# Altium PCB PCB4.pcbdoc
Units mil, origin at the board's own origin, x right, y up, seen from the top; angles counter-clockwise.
Board outline 2975.8 x 1882.95 mil, 2 copper layers (Top Layer, Bottom Layer); 34 components, 33 nets, 157 pads, 29 vias.
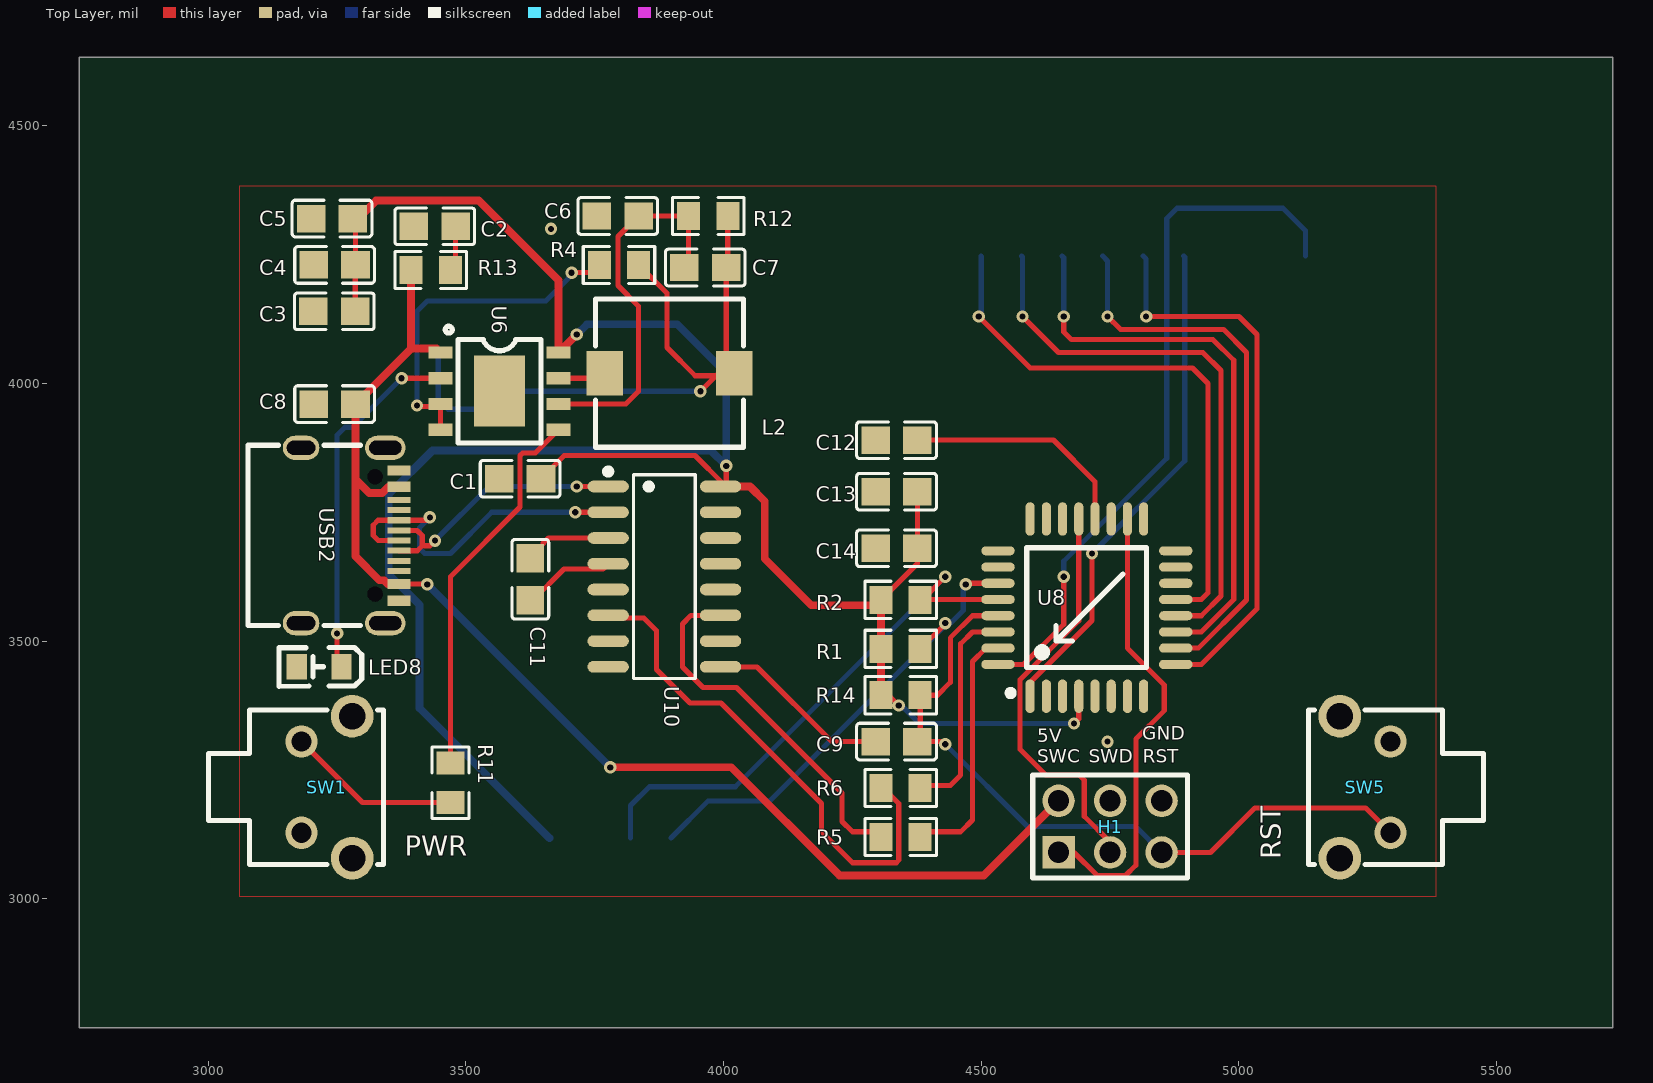
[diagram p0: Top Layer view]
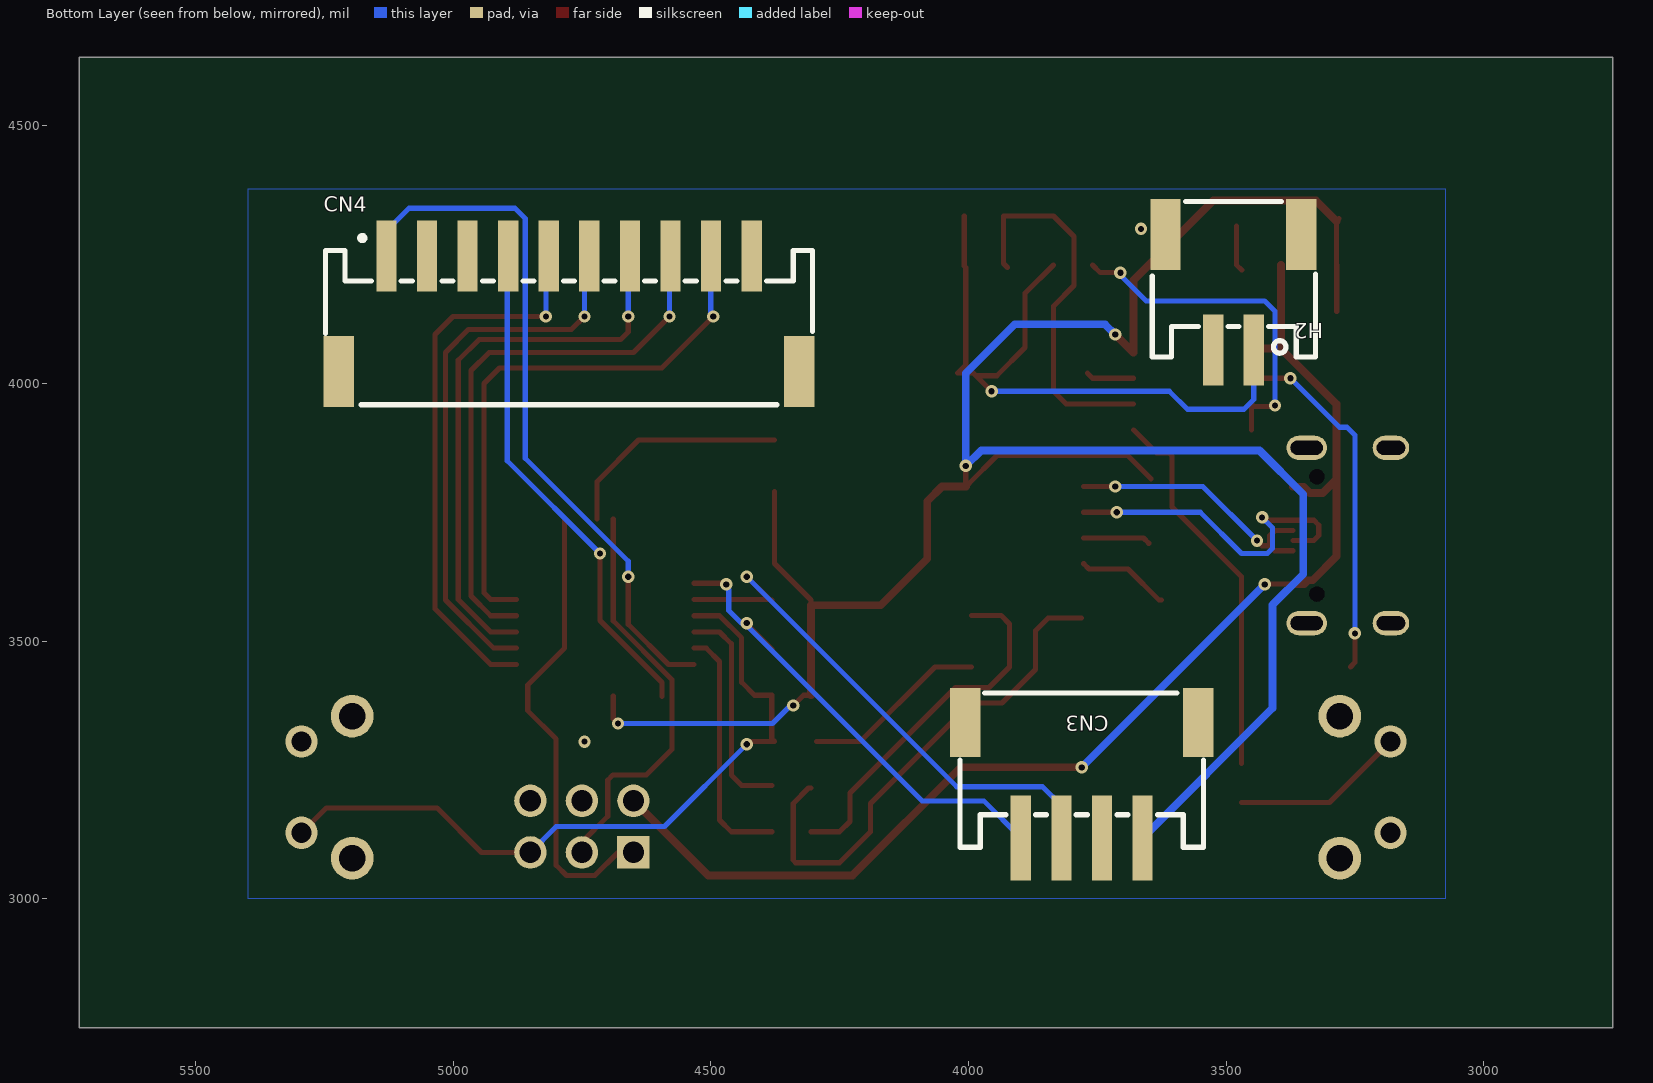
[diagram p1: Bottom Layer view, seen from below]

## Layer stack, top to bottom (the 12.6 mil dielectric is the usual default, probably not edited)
Top Solder: solder mask 0.4, Solder Resist, Dk 3.5
Top Layer: signal copper 1.4
Dielectric 1: dielectric 12.6, FR-4, Dk 4.8
Bottom Layer: signal copper 1.4
Bottom Solder: solder mask 0.4, Solder Resist, Dk 3.5

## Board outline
5725.8,2750 2750,2750 2750,4632.95 5725.8,4632.95

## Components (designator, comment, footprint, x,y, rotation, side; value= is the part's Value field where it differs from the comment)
C1 "104" C0805 3605.4,3815 r0 top
C2 "0.1u" C0805 3439.85,4305 r0 top
C3 "22u" C0805 3244.85,4140 r0 top
C4 "22u" C0805 3245.4,4230 r0 top
C5 "22u" C0805 3240.4,4320 r0 top
C6 "22u" C0805 3794.85,4325 r180 top
C7 "22u" C0805 3964.85,4225 r180 top
C8 "10uF" C0805 3245.4,3960 r180 top
C9 "104" C0805 4335.95,3305 r0 top
C11 "104" C0805 3625.4,3620 r270 top
C12 "104" C0805 4335.95,3890 r0 top
C13 "104" C0805 4335.95,3790 r0 top
C14 "10uF" C0805 4335.95,3680 r0 top
CN3 "HDGC2001WR-S-4P" CONN-SMD_4P-P2.00_HDGC_HDGC2001WR-S-4P 3780.4,3230 r0 bottom
CN4 "WAFER-PH2.0-10PWB" CONN-TH_10P-P2.00_XUNPU_WAFER-PH2.0-10PWB 4775.4,4135 r180 bottom
H1 "ICSP" HDR-TH_6P-P2.54-V-F-R2-C3-S2.54_A2541WV-2X3P 4750.4,3140 r0 top
H2 "WAFER-PH2.0-2PWB" CONN-SMD_2P-P2.00_XUNPU_WAFER-PH2.0-2PWB 3486.03,4177.2 r0 bottom
L2 "1uH" IND-SMD_L7.3-W7.3_YPRH0704 3895.4,4020 r0 top
LED8 "25%" LED0805-RD_RED 3215.4,3450 r180 top
R1 "4.7K" R0805_NEW 4343.92,3485 r180 top
R2 "4.7K" R0805_NEW 4343.92,3580 r180 top
R4 "1K" R0805_NEW 3797.36,4230 r0 top
R5 "1k" R0805_NEW 4343.92,3120 r180 top
R6 "1k" R0805_NEW 4343.92,3215 r180 top
R11 "10K" R0805_NEW 3470.4,3225 r270 top
R12 "0.5r" R0805_NEW 3970.4,4325 r180 top
R13 "2R" R0805_NEW 3431.88,4220 r180 top
R14 "10K" R0805_NEW 4343.92,3395 r0 top
SW1 "KH-6X6X6H-ZJ" SW-TH_KH-6X6X6H-ZJ-A 3230.4,3216.54 r270 top
SW5 "KH-6X6X6H-ZJ" SW-TH_KH-6X6X6H-ZJ-A 5245.4,3216.54 r90 top
U6 "IP5306" ESOP-8_L4.9-W3.9-P1.27-LS6.0-BL-EP 3565.4,3985 r270 top
U8 "LGT8F328P" "LGT328 TQFP-32_" 4705.4,3565 r0 top
U10 "HT42B534-2" NSOP-16_L9.9-W3.9-P1.27-LS6.0-BL 3885.4,3625 r270 top
USB2 "TYPE-C-2.0-16PIN-SMT-3" TYPE-C-SMD_TYPE-CF3.1 3275.4,3705 r270 top

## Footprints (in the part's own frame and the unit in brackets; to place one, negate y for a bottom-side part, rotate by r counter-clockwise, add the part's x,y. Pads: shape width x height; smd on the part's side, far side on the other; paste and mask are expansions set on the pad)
C0805 [mm]
  rect 1.41x1.35 smd: 1(-1.03,0) 2(1.03,0)
  silkscreen extent -1.96,-0.9 1.96,0.9
CONN-SMD_2P-P2.00_XUNPU_WAFER-PH2.0-2PWB [mm]
  rect 1x3.5 smd: 1(-1,2.85) 2(1,2.85)
  rect 1.5x3.5 smd: 4(3.35,-2.85) 5(-3.35,-2.85)
  silkscreen extent -4.05,-4.47 4,3.2
CONN-SMD_4P-P2.00_HDGC_HDGC2001WR-S-4P [mm]
  rect 1x4.2 smd: 1(-3,2.85) 2(-1,2.85) 3(1,2.85) 4(3,2.85)
  rect 1.5x3.4 smd: 5(5.75,-2.85) 6(-5.75,-2.85)
  silkscreen extent -6,-4.3 6,3.3
CONN-TH_10P-P2.00_XUNPU_WAFER-PH2.0-10PWB [mm]
  rect 1x3.5 smd: 1(-9,2.85) 2(-7,2.85) 3(-5,2.85) 4(-3,2.85) 5(-1,2.85) 6(1,2.85) 7(3,2.85) 8(5,2.85) 9(7,2.85) 10(9,2.85)
  rect 1.5x3.5 smd: 11(11.35,-2.85) 12(-11.35,-2.85)
  silkscreen extent -12,-4.47 12,3.87
ESOP-8_L4.9-W3.9-P1.27-LS6.0-BL-EP [mm]
  rect 0.6x1.2 smd: 1(-1.905,-2.908) 2(-0.635,-2.908) 3(0.635,-2.908) 4(1.905,-2.908) 5(1.905,2.908) 6(0.635,2.908) 7(-0.635,2.908) 8(-1.905,2.908)
  rect 3.5x2.5 smd: 9(0,0)
  silkscreen extent -3.2,-2.67 2.55,2.05
HDR-TH_6P-P2.54-V-F-R2-C3-S2.54_A2541WV-2X3P [mm]
  rect 1.6x1.6 hole 1.05: 1(-2.54,-1.27)
  round 1.6 hole 1.05: 2(-2.54,1.27) 3(0,-1.27) 4(0,1.27) 5(2.54,-1.27) 6(2.54,1.27)
  silkscreen extent -3.81,-2.54 3.81,2.54
IND-SMD_L7.3-W7.3_YPRH0704 [mm]
  rect 1.8x2.2 smd: 1(-3.2,0) 2(3.2,0)
  silkscreen extent -3.65,-3.65 3.65,3.65
LED0805-RD_RED [mm]
  rect 1x1.25 smd: 1(-1.1,0) 2(1.1,0)
  silkscreen extent -2.1,-0.95 1.98,0.96
"LGT328 TQFP-32_" [mil]
  oval 17.7x65 smd: 1(-110.2,-172) 2(-78.7,-172) 3(-47.2,-172) 4(-15.7,-172) 5(15.7,-172) 6(47.2,-172) 7(78.7,-172) 8(110.2,-172) 17(110.2,172) 18(78.7,172) 19(47.2,172) 20(15.7,172) 21(-15.7,172) 22(-47.2,172) 23(-78.7,172) 24(-110.2,172)
  oval 65x17.7 smd: 9(172.5,-110.2) 10(172.5,-78.7) 11(172.5,-47.2) 12(172.5,-15.7) 13(172.5,15.7) 14(172.5,47.2) 15(172.5,78.7) 16(172.5,110.2) 25(-172.5,110.2) 26(-172.5,78.7) 27(-172.5,47.2) 28(-172.5,15.7) 29(-172.5,-15.7) 30(-172.5,-47.2) 31(-172.5,-78.7) 32(-172.5,-110.2)
  silkscreen extent -154,-172 116,116
NSOP-16_L9.9-W3.9-P1.27-LS6.0-BL [mil]
  oval 22.6x80.2 smd: 1(-175,-109) 2(-125,-109) 3(-75,-109) 4(-25,-109) 5(25,-109) 6(75,-109) 7(125,-109) 8(175,-109) 9(175,109) 10(125,109) 11(75,109) 12(25,109) 13(-25,109) 14(-75,109) 15(-125,109) 16(-175,109)
  silkscreen extent -210,-115 198,60
R0805_NEW [mil]
  rect 44.59x54.21 smd: 1(-38.04,0) 2(38.04,0)
  silkscreen extent -69,-36 69,36
SW-TH_KH-6X6X6H-ZJ-A [mil]
  round 63 hole 39.4: 1(-88.6,-49.2) 2(88.6,-49.2)
  round 82.7 hole 51.2: 3(-137.8,49.2) 4(137.8,49.2)
  silkscreen extent -150,-230 150,110
TYPE-C-SMD_TYPE-CF3.1 [mm]
  oval 1.2x2 hole 0.7 slot 1.6 at 90 deg: 1(-4.32,1.737) 1(4.32,1.737)
  oval 1.2x1.8 hole 0.7 slot 1.4 at 90 deg: 1(-4.32,-2.413) 1(4.32,-2.413)
  rect 0.5x1.15 smd: A1(-3.2,2.413) A2(-2.4,2.413) A11(2.4,2.413) A12(3.218,2.413)
  rect 0.3x1.15 smd: A3(-1.75,2.413) A4(-1.25,2.413) A5(-0.75,2.413) A6(-0.25,2.413) A7(0.25,2.413) A8(0.75,2.413) A9(1.25,2.413) A10(1.75,2.413)
  Multi-Layer board cut-out: 2.89,1.612 2.727,1.575 2.597,1.471 2.524,1.321 2.524,1.154 2.597,1.004 2.727,0.899 2.89,0.862 2.89,0.862 3.053,0.899 3.183,1.004 3.256,1.154 3.256,1.321 3.183,1.471 3.053,1.575 2.89,1.612
  Multi-Layer board cut-out: -2.89,1.612 -3.053,1.575 -3.183,1.471 -3.256,1.321 -3.256,1.154 -3.183,1.004 -3.053,0.899 -2.89,0.862 -2.89,0.862 -2.727,0.899 -2.597,1.004 -2.524,1.154 -2.524,1.321 -2.597,1.471 -2.727,1.575 -2.89,1.612
  silkscreen extent -4.44,-5.03 4.45,0.52

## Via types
v1: diameter 24.02, hole 12.01, Top Layer to Bottom Layer, 29 vias

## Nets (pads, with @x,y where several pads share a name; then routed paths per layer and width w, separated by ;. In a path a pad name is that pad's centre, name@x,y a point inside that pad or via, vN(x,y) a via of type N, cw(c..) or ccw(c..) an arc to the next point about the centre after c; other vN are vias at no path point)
5V: R14.1 U6.8 U8.4 U10.16 | length 4639.3
  Top Layer w10: 3280.95,4320 3285.95,4315 3285.95,4230 3285.4,4229.45 3285.4,4140 ; 3645.95,3815 3690.95,3860 3944.91,3860 3999.65,3805.25 4005.4,3805.25 v1(4005.4,3840) ; R14.1 4320.4,3395 v1(4340.4,3375) ; 4305.88,3569.72 4305.88,3580 4376.5,3650.62 4376.5,3680 4376.5,3790 ; v1(4680.4,3340) 4689.7,3349.3 U8.4
  Top Layer w15: 3285.95,4315 3325.95,4355 3525.4,4355 3679.9,4200.5 U6.8 3680.4,4060 v1(3715.4,4095) ; U10.16@4004.91,3800 4051.5,3800 4080.4,3771.1 4080.4,3660 4170.68,3569.72 4305.88,3569.72 4305.88,3485 R14.1
  Bottom Layer w10: v1(4340.4,3375) 4345.4,3375 4380.4,3340 v1(4680.4,3340)
  Bottom Layer w15: 3662.29,3117.8 3410.4,3369.68 3410.4,3570 3350.4,3630 3350.4,3785 3435.4,3870 3975.4,3870 v1(4005.4,3840) 4005.4,4020 3910.4,4115 3735.4,4115 v1(3715.4,4095)
5V_IP5306_IN: C8.1 H1.2 USB2.A2 USB2.A11 | length 2452.2
  Top Layer w10: USB2.A11 3424.89,3610.51 v1(3425.4,3610)
  Top Layer w15: USB2.A11 3349.11,3610.51 3341.28,3618.35 3332.05,3618.35 3285.95,3664.45 3285.95,3814.45 ; USB2.A2 3349.88,3799.48 3337.9,3787.5 3312.9,3787.5 3285.95,3814.45 ; 3393.84,4230 3393.84,4067.89 ; 3450.9,4060 3443.01,4067.89 3393.84,4067.89 ; v1(3780.4,3255) 4015.4,3255 4225.4,3045 4505.4,3045 H1.2 ; 3285.95,3814.45 C8.1 3393.84,4067.89
  Bottom Layer w15: v1(3425.4,3610) v1(3780.4,3255)
$1N4498: R5.1 U8.31 | length 478.6
  Top Layer w10: R5.1@4381.96,3130 4460.4,3130 4483.4,3153 4483.4,3460.45 4509.25,3486.3 U8.31
$1N4499: R6.1 U8.30 | length 423.6
  Top Layer w10: R6.1@4381.96,3220 4440.4,3220 4460.4,3240 4460.4,3494.8 4483.4,3517.8 U8.30
$1N4601: U8.20 | length 450.3
  Top Layer w10: 4376.5,3890 4640.4,3890 4721.1,3809.3 U8.20
$1N6976: C9.1 U10.9 | length 361.1
  Top Layer w10: U10.9 4065.4,3450 4210.4,3305 C9.1
$1N7176: C11.1 U10.3 | length 130.1
  Top Layer w10: 3650.4,3690 3660.4,3700 U10.3
$2N28: R11.1 U6.5 | length 748.1
  Top Layer w10: R11.1 3470.4,3625 3605.4,3760 3605.4,3860 3610.4,3865 3634.9,3865 U6.5
$2N29:  | length 338.1
  Top Layer w10: 3181.2,3305.14 3299.38,3186.96 3470.4,3186.96
$2N68: C6.1 U6.6 | length 739.3
  Top Layer w10: U6.6 3810.4,3960 3835.4,3985 3835.4,4150 3795.4,4190 3795.4,4285 C6.1 3932.36,4325 3932.36,4233.06 3924.3,4225
$2N124: U6.7 | length 93.7
  Top Layer w10: U6.7 3759.42,4010 3769.42,4020
$2N158: LED8.1 U6.2 | length 699.5
  Top Layer w10: v1(3250.4,3515) 3250.4,3458.31 LED8.1 ; v1(3375.4,4010) U6.2
  Bottom Layer w10: v1(3250.4,3515) 3250.4,3900 3265.4,3915 3280.4,3915 v1(3375.4,4010)
$2N300: R13.1 | length 89.3
  Top Layer w10: R13.1 3480.4,4230.48 3480.4,4305
$2N3097: R4.1 U6.3 U6.4 | length 659.4
  Top Layer w10: v1@3415.4,3955 3445.9,3955 U6.3 U6.4 ; v1(3705.4,4215) 3744.32,4215 R4.1
  Bottom Layer w10: v1(3405.4,3957.26) 3405.4,4140 3425.4,4160 3655.4,4160 v1@3705.4,4210
BAT: C7.1 L2.2 R12.1 | length 1321.2
  Top Layer w10: 3835.4,4230 3890.4,4175 3890.4,4070 3945.4,4015 3985.4,4015 ; v1(3955.4,3985) 3985.4,4015 ; R12.1 4008.44,4228.04 C7.1 4005.4,4035.98 L2.2 3990.4,4020 3985.4,4015
  Bottom Layer w10: 3446.66,4065 3446.66,3968.74 3465.4,3950 3575.4,3950 3610.4,3985 v1(3955.4,3985)
  other v1: 3955.4,3985
D2: CN4.1 | length 1374.7
  Top Layer w10: 4532.9,3454.8 4582.4,3454.8 4660.4,3532.8 v1(4660.4,3625)
  Bottom Layer w10: v1(4660.4,3625) 4660.4,3655 4860.4,3855 4860.4,4320 4880.4,4340 5086.15,4340 5129.73,4296.42 CN4.1
GND: C1.1 C2.1 C3.1 C4.1 C5.1 C12.1 C13.1 C14.1 CN3.2 CN3.5 CN4.11 CN4.12 H2.2 H2.4 SW1.2 SW1.3 SW5.2 U6.9 U8.5 U10.4 USB2.1 USB2.A1 USB2.A12 | length 180.2
  Top Layer w10: 3625.4,3579.45 3629.85,3579.45 3690.4,3640 3766.4,3640 U10.4
  other v1: 4745.4,3305 3665.4,4300
I2C_SCL: CN3.3 R2.1 U8.28 | length 1071.5
  Top Layer w10: R2.1 4385.4,3580 R2.1@4386.1,3580.7 ; v1(4430.4,3625) R2.1@4386.1,3580.7 ; U8.28 R2.1@4386.1,3580.7
  Bottom Layer w10: CN3.3 3819.77,3180.79 3856.42,3217.44 4022.84,3217.44 v1(4430.4,3625)
I2C_SDA: CN3.4 R1.1 U8.27 | length 926.9
  Top Layer w10: R1.1 4430.4,3533.44 v1(4430.4,3535) ; v1(4470.4,3610) 4472.6,3612.2 U8.27
  Bottom Layer w10: CN3.4 3970.72,3190 4090.4,3190 4430.4,3530 v1(4430.4,3535) 4441.18,3535 4465.4,3559.22 v1@4465.4,3600
LED_C: CN4.4 U8.1 | length 979.3
  Top Layer w10: U8.1 4595.2,3419.8 4715.4,3540 v1(4715.4,3670)
  Bottom Layer w10: v1(4715.4,3670) 4895.4,3850 4895.4,4245.31 CN4.4
OUT: CN4.5 U8.9 | length 1083.5
  Top Layer w10: v1(4820.4,4130) 5000.4,4130 5035.4,4095 5035.4,3562.8 4927.4,3454.8 U8.9
  Bottom Layer w10: CN4.5 4820.4,4241.57 v1(4820.4,4130)
RST: H1.5 U8.29 | length 1420.7
  Top Layer w10: v1(4430.4,3300) 4425.4,3305 4376.5,3305 4381.96,3310.46 4381.96,3395 4415.4,3395 4440.4,3420 4440.4,3506.3 4483.4,3549.3 U8.29 ; H1.5 4945.4,3090 5031.8,3176.4 5246.13,3176.4 5294.6,3127.94
  Bottom Layer w10: v1(4430.4,3300) 4590.4,3140 4800.4,3140 H1.5
RXD: U10.6 | length 990.9
  Top Layer w10: U10.6@3781.4,3545 3845.4,3545 3870.4,3520 3870.4,3445 3935.4,3380 3995.4,3380 4190.4,3185 4190.4,3130 4250.4,3070 4335.4,3070 4340.4,3075 4340.4,3185 4310.4,3215 4305.88,3215
S0: CN4.8 U8.12 | length 1087.4
  Top Layer w10: v1(4580.4,4130) 4650.4,4060 4930.4,4060 4965.4,4025 4965.4,3587.3 4927.4,3549.3 U8.12
  Bottom Layer w10: CN4.8 4580.4,4245.35 v1(4580.4,4130)
S1: CN4.9 U8.13 | length 1095.5
  Top Layer w10: v1(4495.4,4130) 4595.4,4030 4910.4,4030 4940.4,4000 4940.4,3593.7 4927.4,3580.7 U8.13
  Bottom Layer w10: v1(4495.4,4130) 4500.4,4130 4500.4,4246.61 CN4.9
S2: CN4.6 U8.10 | length 1076.4
  Top Layer w10: v1(4745.4,4130) 4770.4,4105 4970.4,4105 5015.4,4060 5015.4,3580 4921.7,3486.3 U8.10
  Bottom Layer w10: CN4.6 4745.4,4237.84 v1(4745.4,4130)
S3: CN4.7 U8.11 | length 1104.1
  Top Layer w10: v1(4660.4,4130) 4660.4,4100 4675.4,4085 4950.4,4085 4990.4,4045 4990.4,3580.8 4927.4,3517.8 U8.11
  Bottom Layer w10: CN4.7 4660.4,4244.1 v1(4660.4,4130)
SWC: H1.1 U8.18 | length 901.2
  Top Layer w10: H1.1 4680.4,3090 4725.4,3045 4780.4,3045 4800.4,3065 4800.4,3310 4855.4,3365 4855.4,3415 4784.1,3486.3 U8.18
SWD: H1.3 U8.21 | length 804.9
  Top Layer w10: U8.21 4689.7,3539.3 4575.35,3424.95 4575.35,3290.05 4625.4,3240 4690.4,3240 4700.4,3230 4700.4,3160 4750.4,3110 H1.3
TXD: U10.11 | length 714.3
  Top Layer w10: U10.11 3937.3,3550 3920.4,3533.1 3920.4,3450 3960.4,3410 4025.4,3410 4230.4,3205 4230.4,3150 4250.4,3130 4305.88,3130
USB_DN: U10.2 USB2.A5 USB2.A7 | length 654.7
  Top Layer w10: USB2.A7 3330.25,3695.15 3320.4,3705 3320.4,3725 3329.92,3734.52 USB2.A5 3424.92,3734.52 v1(3430.4,3740) ; v1(3712.57,3750) U10.2
  Bottom Layer w10: v1(3430.4,3740) 3410.4,3720 3410.4,3680 3420.4,3670 3470.4,3670 3550.4,3750 v1@3705.4,3750
USB_DP: USB2.A6 USB2.A8 | length 526.7
  Top Layer w10: USB2.A8 3405.87,3675.47 3415.4,3685 ; USB2.A6 3405.56,3714.84 3415.4,3705 3415.4,3685 ; v1(3440.4,3695) 3430.4,3685 3415.4,3685 ; v1(3715.4,3800) 3776.4,3800
  Bottom Layer w10: v1(3440.4,3695) 3545.4,3800 v1(3715.4,3800)
"": 
pads on no net: C1.2 C2.2 C3.2 C4.2 C5.2 C6.2 C7.2 C8.2 C9.2 C11.2 C12.2 C13.2 C14.2 CN3.1 CN3.6 CN4.2 CN4.3 CN4.10 H1.4 H1.6 H2.1 H2.5 L2.1 LED8.2 R1.2 R2.2 R4.2 R5.2 R6.2 R11.2 R12.2 R13.2 R14.2 SW1.1 SW1.4 SW5.1 SW5.3 SW5.4 U6.1 U8.2 U8.3 U8.6 U8.7 U8.8 U8.14 U8.15 U8.16 U8.17 U8.19 U8.22 U8.23 U8.24 U8.25 U8.26 U8.32 U10.1 U10.5 U10.7 U10.8 U10.10 U10.12 U10.13 U10.14 U10.15 USB2.A3 USB2.A4 USB2.A9 USB2.A10

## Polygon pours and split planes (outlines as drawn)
GND on Top Layer (solid, remove dead copper): 3060.4,3005 5383.23,3005 5383.23,4382.95 3060.4,4382.95
GND on Bottom Layer (solid, remove dead copper, pour order 1): 3075.4,3000 5398.23,3000 5398.23,4377.95 3075.4,4377.95

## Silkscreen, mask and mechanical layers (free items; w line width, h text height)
Top Overlay:
  text "GND" at 4812.48,3308.88 h25.96
  text "5V" at 4609.32,3303.88 h25.96
  text "SWC" at 4609.13,3263.88 h25.96
  text "SWD" at 4708.63,3263.88 h25.96
  text "RST" at 4814.18,3263.88 h25.96
  text "PWR" at 3381.38,3083.32 h38.94
  text "RST" at 5082.08,3076.68 h38.94 r90
Mechanical 1:
  lines w10: 3075.4,3000 5398.23,3000 5398.23,4377.95 3075.4,4377.95 3075.4,3000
